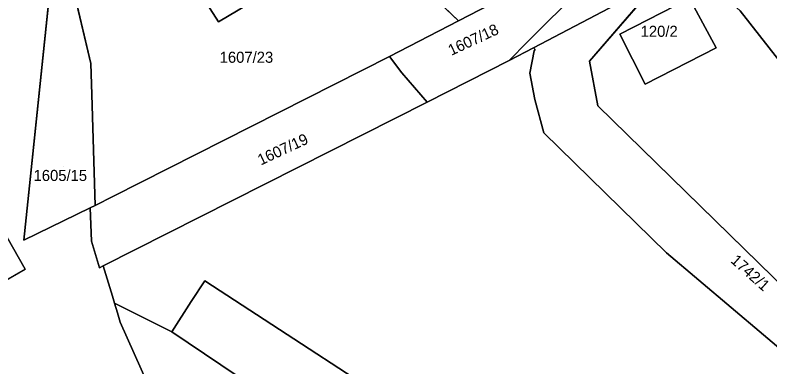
# Model space of a CAD drawing. Extents: x -263943 to -261149, y -1236934 to -1230686.
# Drawn here: x -262681.2 to -262544.9, y -1236039.5 to -1235975.9 of the extents above; entities that cross this region are included whole.
import ezdxf

# ---------------------------------------------------------------- set-up
doc = ezdxf.new("R2010")
doc.units = 0
for name, color, linetype in [('body_kn', 7, 'Continuous'), ('kladpar_druhypozemkov', 7, 'Continuous'), ('kladpar_hranice', 7, 'Continuous'), ('kladpar_parcelnecisla', 7, 'Continuous'), ('kladpar_plochy', 7, 'Continuous')]:
    doc.layers.add(name, color=color, linetype=linetype)

msp = doc.modelspace()

# ---------------------------------------------------------------- linework, layer by layer
at = {"layer": 'body_kn'}
for p, q in [((-262644.45, -1235977.14), (-262644.45, -1235977.14)), ((-262601.07, -1235977), (-262601.07, -1235977)), ((-262601.07, -1235977), (-262601.07, -1235977)), ((-262571.98, -1235979.37), (-262571.98, -1235979.37)), ((-262571.98, -1235979.37), (-262571.98, -1235979.37)), ((-262588.6, -1235980.8), (-262588.6, -1235980.8)), ((-262587.56, -1235981.84), (-262587.56, -1235981.84)), ((-262587.23, -1235982.17), (-262587.23, -1235982.17)), ((-262554.57, -1235981.87), (-262554.57, -1235981.87)), ((-262613.53, -1235983.41), (-262613.53, -1235983.41)), ((-262613.53, -1235983.41), (-262613.53, -1235983.41)), ((-262587.45, -1235982.38), (-262587.45, -1235982.38)), ((-262667.48, -1235984.71), (-262667.48, -1235984.71)), ((-262591.95, -1235984.15), (-262591.95, -1235984.15)), ((-262591.95, -1235984.15), (-262591.95, -1235984.15)), ((-262577.42, -1235984.27), (-262577.42, -1235984.27)), ((-262611.33, -1235986.39), (-262611.33, -1235986.39)), ((-262588.22, -1235986.45), (-262588.22, -1235986.45)), ((-262567.4, -1235988.45), (-262567.4, -1235988.45)), ((-262667.31, -1235990.3), (-262667.31, -1235990.3)), ((-262606.74, -1235991.66), (-262606.74, -1235991.66)), ((-262587.29, -1235991.2), (-262587.29, -1235991.2)), ((-262575.9, -1235992.33), (-262575.9, -1235992.33)), ((-262585.67, -1235997.22), (-262585.67, -1235997.22)), ((-262663.41, -1236008.69), (-262663.41, -1236008.69)), ((-262667.58, -1236010.8), (-262667.58, -1236010.8)), ((-262667.58, -1236010.8), (-262667.58, -1236010.8)), ((-262666.71, -1236010.36), (-262666.71, -1236010.36)), ((-262666.71, -1236010.36), (-262666.71, -1236010.36)), ((-262679.57, -1236016.6), (-262679.57, -1236016.6)), ((-262667.35, -1236016.8), (-262667.35, -1236016.8)), ((-262563.54, -1236018.94), (-262563.54, -1236018.94)), ((-262665.94, -1236021.62), (-262665.94, -1236021.62)), ((-262665.23, -1236021.26), (-262665.23, -1236021.26)), ((-262665.23, -1236021.26), (-262665.23, -1236021.26)), ((-262679.32, -1236021.89), (-262679.32, -1236021.89)), ((-262646.9, -1236024), (-262646.9, -1236024)), ((-262663.59, -1236026.73), (-262663.59, -1236026.73)), ((-262663.21, -1236027.99), (-262663.21, -1236027.99)), ((-262649.33, -1236027.73), (-262649.33, -1236027.73)), ((-262662.69, -1236029.75), (-262662.69, -1236029.75)), ((-262662.18, -1236031.44), (-262662.18, -1236031.44)), ((-262652.87, -1236033.18), (-262652.87, -1236033.18))]:
    msp.add_line(p, q, dxfattribs=at)
at = {"layer": 'kladpar_druhypozemkov'}
for p, q in [((-262564.31, -1235978.03), (-262564.31, -1235978.03)), ((-262598, -1235978.8), (-262598, -1235978.8)), ((-262638.39, -1235982.42), (-262638.39, -1235982.42)), ((-262633.78, -1235999.25), (-262633.78, -1235999.25)), ((-262672.4, -1236003.23), (-262672.4, -1236003.23))]:
    msp.add_line(p, q, dxfattribs=at)
at = {"layer": 'kladpar_hranice'}
for p, q in [((-262601.07, -1235977), (-262613.53, -1235983.41)), ((-262666.71, -1236010.36), (-262667.58, -1236010.8))]:
    msp.add_line(p, q, dxfattribs=at)
for points in [[(-262637.63, -1235941.97), (-262632.86, -1235946.54), (-262601.07, -1235977)], [(-262601.07, -1235977), (-262632.86, -1235946.54), (-262637.63, -1235941.97)], [(-262620.13, -1235949.3), (-262595.35, -1235974.06), (-262601.07, -1235977)], [(-262644.45, -1235977.14), (-262633.74, -1235970.81), (-262642.23, -1235958.83), (-262652.17, -1235964.99), (-262644.45, -1235977.14)], [(-262652.17, -1235964.99), (-262642.23, -1235958.83), (-262633.74, -1235970.81), (-262644.45, -1235977.14), (-262652.17, -1235964.99)], [(-262667.58, -1236010.8), (-262679.57, -1236016.6), (-262674.51, -1235968.02), (-262673.59, -1235959.19)], [(-262673.59, -1235959.19), (-262674.51, -1235968.02), (-262679.57, -1236016.6), (-262667.58, -1236010.8)], [(-262667.48, -1235984.71), (-262673.15, -1235960.61), (-262673.59, -1235959.19)], [(-262673.59, -1235959.19), (-262673.15, -1235960.61), (-262667.48, -1235984.71), (-262667.31, -1235990.3), (-262666.71, -1236010.36)], [(-262565.17, -1235961.41), (-262561.02, -1235965.27), (-262559.23, -1235966.94), (-262565.15, -1235970.05), (-262587.56, -1235981.84), (-262591.95, -1235984.15), (-262588.6, -1235980.8), (-262569.45, -1235961.6), (-262570.11, -1235961.07), (-262567.29, -1235959.62), (-262565.17, -1235961.41)], [(-262537.84, -1235980.27), (-262543.27, -1235984.11), (-262550.23, -1235975.18), (-262559.23, -1235966.94), (-262561.02, -1235965.27), (-262565.17, -1235961.41), (-262567.29, -1235959.62)], [(-262591.95, -1235984.15), (-262606.74, -1235991.66), (-262611.33, -1235986.39), (-262613.53, -1235983.41), (-262601.07, -1235977), (-262595.35, -1235974.06), (-262570.11, -1235961.07), (-262569.45, -1235961.6), (-262588.6, -1235980.8), (-262591.95, -1235984.15)], [(-262454.23, -1236090.06), (-262452.27, -1236092.3), (-262432.56, -1236114.81), (-262419.82, -1236129.36), (-262434.89, -1236127.22), (-262450.45, -1236112.95), (-262479.63, -1236085.6), (-262520.39, -1236046.71), (-262575.9, -1235992.33), (-262577.42, -1235984.27), (-262565.15, -1235970.05), (-262559.23, -1235966.94), (-262550.23, -1235975.18), (-262543.27, -1235984.11), (-262541.02, -1235986.91), (-262506.13, -1236030.26), (-262500.06, -1236037.34), (-262486.53, -1236053.13)], [(-262434.89, -1236127.22), (-262444.34, -1236126.9), (-262456.72, -1236115.4), (-262483.62, -1236089.75), (-262513.59, -1236060.86), (-262534.35, -1236043.6), (-262563.54, -1236018.94), (-262585.67, -1235997.22), (-262587.29, -1235991.2), (-262588.22, -1235986.45), (-262587.45, -1235982.38), (-262587.23, -1235982.17), (-262587.56, -1235981.84), (-262565.15, -1235970.05), (-262577.42, -1235984.27), (-262575.9, -1235992.33), (-262520.39, -1236046.71), (-262479.63, -1236085.6), (-262450.45, -1236112.95), (-262434.89, -1236127.22)], [(-262571.98, -1235979.37), (-262559.4, -1235972.87), (-262554.57, -1235981.87), (-262567.4, -1235988.45), (-262571.98, -1235979.37)], [(-262567.4, -1235988.45), (-262554.57, -1235981.87), (-262559.4, -1235972.87), (-262571.98, -1235979.37), (-262567.4, -1235988.45)], [(-262704.17, -1235978.09), (-262679.32, -1236021.89), (-262685.35, -1236025.32)], [(-262685.35, -1236025.32), (-262679.32, -1236021.89), (-262704.17, -1235978.09)], [(-262537.33, -1236097.92), (-262566.2, -1236078.33), (-262603.85, -1236052.03), (-262646.9, -1236024), (-262649.33, -1236027.73), (-262652.87, -1236033.18), (-262663.21, -1236027.99), (-262663.59, -1236026.73), (-262665.23, -1236021.26), (-262606.74, -1235991.66), (-262591.95, -1235984.15), (-262587.56, -1235981.84), (-262587.23, -1235982.17), (-262587.45, -1235982.38), (-262588.22, -1235986.45), (-262587.29, -1235991.2), (-262585.67, -1235997.22), (-262563.54, -1236018.94), (-262534.35, -1236043.6)], [(-262665.23, -1236021.26), (-262665.94, -1236021.62), (-262667.35, -1236016.8), (-262667.58, -1236010.8), (-262666.71, -1236010.36), (-262663.41, -1236008.69), (-262613.53, -1235983.41), (-262611.33, -1235986.39), (-262606.74, -1235991.66), (-262665.23, -1236021.26)], [(-262613.53, -1235983.41), (-262663.41, -1236008.69), (-262666.71, -1236010.36), (-262667.31, -1235990.3), (-262667.48, -1235984.71)], [(-262667.58, -1236010.8), (-262667.35, -1236016.8), (-262665.94, -1236021.62), (-262665.23, -1236021.26), (-262663.59, -1236026.73), (-262663.21, -1236027.99), (-262662.69, -1236029.75), (-262662.18, -1236031.44), (-262649.76, -1236059.19)], [(-262438.46, -1236136.62), (-262477.49, -1236134.43), (-262500.18, -1236127.78), (-262511.03, -1236125.02), (-262524.89, -1236118.94), (-262549.15, -1236124.23), (-262573.98, -1236093.25), (-262606.03, -1236064.77), (-262652.87, -1236033.18), (-262649.33, -1236027.73), (-262646.9, -1236024), (-262603.85, -1236052.03), (-262566.2, -1236078.33), (-262537.33, -1236097.92), (-262506.14, -1236112.45), (-262482.81, -1236120.01), (-262448.01, -1236126.77), (-262444.34, -1236126.9), (-262434.89, -1236127.22), (-262419.82, -1236129.36), (-262418.31, -1236129.53), (-262399.93, -1236131.65), (-262396.62, -1236132.03), (-262393.32, -1236133.05)], [(-262509.98, -1236213.81), (-262499.75, -1236243.51), (-262577.14, -1236270.68), (-262597.53, -1236212.99), (-262579.87, -1236205.14), (-262582.7, -1236199.47), (-262614.93, -1236134.79), (-262615.42, -1236130.65), (-262615.29, -1236130.57), (-262610.06, -1236127.29), (-262644.44, -1236056.8), (-262649.03, -1236058.86), (-262649.76, -1236059.19), (-262662.18, -1236031.44), (-262662.69, -1236029.75), (-262663.21, -1236027.99), (-262652.87, -1236033.18), (-262606.03, -1236064.77), (-262573.98, -1236093.25), (-262549.15, -1236124.23), (-262528.24, -1236160.77), (-262509.98, -1236213.81)]]:
    msp.add_lwpolyline(points, dxfattribs=at)
at = {"layer": 'kladpar_plochy'}
for p, q in [((-262632.86, -1235946.54), (-262601.07, -1235977)), ((-262667.48, -1235984.71), (-262673.15, -1235960.61)), ((-262652.17, -1235964.99), (-262644.45, -1235977.14)), ((-262674.51, -1235968.02), (-262679.57, -1236016.6)), ((-262644.45, -1235977.14), (-262633.74, -1235970.81)), ((-262577.42, -1235984.27), (-262565.15, -1235970.05)), ((-262559.4, -1235972.87), (-262571.98, -1235979.37)), ((-262554.57, -1235981.87), (-262559.4, -1235972.87)), ((-262550.23, -1235975.18), (-262543.27, -1235984.11)), ((-262679.32, -1236021.89), (-262704.17, -1235978.09)), ((-262601.07, -1235977), (-262613.53, -1235983.41)), ((-262571.98, -1235979.37), (-262567.4, -1235988.45)), ((-262567.4, -1235988.45), (-262554.57, -1235981.87)), ((-262613.53, -1235983.41), (-262663.41, -1236008.69)), ((-262667.31, -1235990.3), (-262667.48, -1235984.71)), ((-262575.9, -1235992.33), (-262577.42, -1235984.27)), ((-262666.71, -1236010.36), (-262667.31, -1235990.3)), ((-262520.39, -1236046.71), (-262575.9, -1235992.33)), ((-262663.41, -1236008.69), (-262666.71, -1236010.36)), ((-262679.57, -1236016.6), (-262667.58, -1236010.8)), ((-262667.58, -1236010.8), (-262667.35, -1236016.8)), ((-262667.35, -1236016.8), (-262665.94, -1236021.62)), ((-262665.94, -1236021.62), (-262665.23, -1236021.26)), ((-262665.23, -1236021.26), (-262663.59, -1236026.73)), ((-262685.35, -1236025.32), (-262679.32, -1236021.89)), ((-262663.59, -1236026.73), (-262663.21, -1236027.99)), ((-262663.21, -1236027.99), (-262662.69, -1236029.75)), ((-262662.69, -1236029.75), (-262662.18, -1236031.44)), ((-262662.18, -1236031.44), (-262649.76, -1236059.19))]:
    msp.add_line(p, q, dxfattribs=at)
for points in [[(-262620.13, -1235949.3), (-262595.35, -1235974.06), (-262601.07, -1235977), (-262632.86, -1235946.54), (-262637.63, -1235941.97), (-262636.86, -1235941.97), (-262634.48, -1235944.6), (-262629.38, -1235940.21), (-262624.46, -1235945.05), (-262627.86, -1235948.27), (-262623.53, -1235952.52)], [(-262652.17, -1235964.99), (-262642.23, -1235958.83), (-262633.74, -1235970.81), (-262644.45, -1235977.14)], [(-262666.71, -1236010.36), (-262667.58, -1236010.8), (-262679.57, -1236016.6), (-262674.51, -1235968.02), (-262673.59, -1235959.19), (-262673.15, -1235960.61), (-262667.48, -1235984.71), (-262667.31, -1235990.3)], [(-262565.17, -1235961.41), (-262561.02, -1235965.27), (-262559.23, -1235966.94), (-262565.15, -1235970.05), (-262587.56, -1235981.84), (-262591.95, -1235984.15), (-262588.6, -1235980.8), (-262569.45, -1235961.6), (-262570.11, -1235961.07), (-262567.29, -1235959.62)], [(-262591.95, -1235984.15), (-262606.74, -1235991.66), (-262611.33, -1235986.39), (-262613.53, -1235983.41), (-262601.07, -1235977), (-262595.35, -1235974.06), (-262570.11, -1235961.07), (-262569.45, -1235961.6), (-262588.6, -1235980.8)], [(-262434.89, -1236127.22), (-262444.34, -1236126.9), (-262456.72, -1236115.4), (-262483.62, -1236089.75), (-262513.59, -1236060.86), (-262534.35, -1236043.6), (-262563.54, -1236018.94), (-262585.67, -1235997.22), (-262587.29, -1235991.2), (-262588.22, -1235986.45), (-262587.45, -1235982.38), (-262587.23, -1235982.17), (-262587.56, -1235981.84), (-262565.15, -1235970.05), (-262577.42, -1235984.27), (-262575.9, -1235992.33), (-262520.39, -1236046.71), (-262479.63, -1236085.6), (-262450.45, -1236112.95)], [(-262571.98, -1235979.37), (-262559.4, -1235972.87), (-262554.57, -1235981.87), (-262567.4, -1235988.45)], [(-262665.23, -1236021.26), (-262665.94, -1236021.62), (-262667.35, -1236016.8), (-262667.58, -1236010.8), (-262666.71, -1236010.36), (-262663.41, -1236008.69), (-262613.53, -1235983.41), (-262611.33, -1235986.39), (-262606.74, -1235991.66)], [(-262509.98, -1236213.81), (-262499.75, -1236243.51), (-262577.14, -1236270.68), (-262597.53, -1236212.99), (-262579.87, -1236205.14), (-262582.7, -1236199.47), (-262614.93, -1236134.79), (-262615.42, -1236130.65), (-262615.29, -1236130.57), (-262610.06, -1236127.29), (-262644.44, -1236056.8), (-262649.03, -1236058.86), (-262649.76, -1236059.19), (-262662.18, -1236031.44), (-262662.69, -1236029.75), (-262663.21, -1236027.99), (-262652.87, -1236033.18), (-262606.03, -1236064.77), (-262573.98, -1236093.25), (-262549.15, -1236124.23), (-262528.24, -1236160.77)]]:
    msp.add_lwpolyline(points, close=True, dxfattribs=at)
for points in [[(-262543.27, -1235984.11), (-262550.23, -1235975.18)], [(-262704.17, -1235978.09), (-262679.32, -1236021.89), (-262685.35, -1236025.32)], [(-262537.33, -1236097.92), (-262566.2, -1236078.33), (-262603.85, -1236052.03), (-262646.9, -1236024), (-262649.33, -1236027.73), (-262652.87, -1236033.18), (-262663.21, -1236027.99), (-262663.59, -1236026.73), (-262665.23, -1236021.26), (-262606.74, -1235991.66), (-262591.95, -1235984.15), (-262587.56, -1235981.84), (-262587.23, -1235982.17), (-262587.45, -1235982.38), (-262588.22, -1235986.45), (-262587.29, -1235991.2), (-262585.67, -1235997.22), (-262563.54, -1236018.94), (-262534.35, -1236043.6)], [(-262438.46, -1236136.62), (-262477.49, -1236134.43), (-262500.18, -1236127.78), (-262511.03, -1236125.02), (-262524.89, -1236118.94), (-262549.15, -1236124.23), (-262573.98, -1236093.25), (-262606.03, -1236064.77), (-262652.87, -1236033.18), (-262649.33, -1236027.73), (-262646.9, -1236024), (-262603.85, -1236052.03), (-262566.2, -1236078.33), (-262537.33, -1236097.92), (-262506.14, -1236112.45), (-262482.81, -1236120.01), (-262448.01, -1236126.77), (-262444.34, -1236126.9), (-262434.89, -1236127.22), (-262419.82, -1236129.36), (-262418.31, -1236129.53), (-262399.93, -1236131.65), (-262396.62, -1236132.03), (-262393.32, -1236133.05)]]:
    msp.add_lwpolyline(points, dxfattribs=at)

# ---------------------------------------------------------------- texts
at = {"layer": 'kladpar_parcelnecisla'}
for s, rotation, p in [('1607/18', 25, (-262602.39, -1235983.33)), ('1607/19', 25, (-262636.78, -1236003.15)), ('1742/1', 318, (-262552.09, -1236020.51))]:
    msp.add_text(s, height=2, rotation=rotation, dxfattribs=at).set_placement(p)
for s, p in [('120/2', (-262568.19, -1235979.88)), ('1607/23', (-262644.21, -1235984.57)), ('1605/15', (-262677.82, -1236005.93))]:
    msp.add_text(s, height=2, dxfattribs=at).set_placement(p)

doc.saveas('drawing.dxf')
